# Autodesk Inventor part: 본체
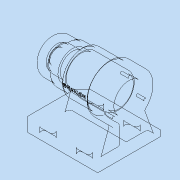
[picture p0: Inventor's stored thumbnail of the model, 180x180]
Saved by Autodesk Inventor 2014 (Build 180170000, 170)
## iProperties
Created: 2017-09
Part Number: 본체
Material: 알루미늄 6061
Document SubType Name: Modeling
Designer: kb542-16
Mass: 696.175 g
Surface Area: 708.751 cm^2
Volume: 256.891 cm^3
Density: 2.71 g/cm^3
Appearance: 알루미늄 - 평지
Author: kb542-16
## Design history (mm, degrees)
sketch "스케치2"
  geometry: L1 (-56, -45)-(56, -45); L2 (56, -45)-(56, 45); L3 (56, 45)-(-56, 45); L4 (-56, 45)-(-56, -45); L5 (-56, -45)-(56, 45); L6 (56, -45)-(-56, 45); 1 further point
  constraints: 12 end point, 2 midpoint, 2 parallel, 1 horizontal, 1 perpendicular
  dimensions: "d4" = 112 distance between parallel lines of L4 L2; "d5" = 90 distance between parallel lines of L1 L3
extrude "돌출1" new body sketch "스케치2" distance "d6" = 8; taper "d7" = 0 deg
chamfer "모따기1" distance "d8" = 12; stored, may be unused: second distance "d9" = 2, angle "d10" = 45 deg
sketch "스케치3"
  geometry: L1 (-32, 34)-(-20, 34); L2 (-32, 30)-(-20, 30); L3 (-20, 38)-(-32, 38); L4 (20, 34)-(32, 34); L5 (20, 30)-(32, 30); L6 (32, 38)-(20, 38); L7 (56, -45)-(56, 45) reference; A1 r 4 centre (-32, 34) between (-32, 38) and (-32, 30); A2 r 4 centre (-20, 34) between (-20, 30) and (-20, 38); A3 r 4 centre (20, 34) between (20, 38) and (20, 30); A4 r 4 centre (32, 34) between (32, 30) and (32, 38); 3 further points
  constraints: 16 end point, 8 point on circle, 8 tangent, 4 centre point, 3 equal length, 2 midpoint, 1 horizontal
  dimensions: "d11" = 12 distance of L1.end L1.start; "d12" = 4 radius of A1; "d13" = 34 vertical distance of point (0, 0) point (-26, 34); "d15" = 24 distance from line of L7 L4.end; "d16" = 40 distance of L4.start L1.end; "d17" = 12 distance of L5.start L5.end; "d18" = 4 radius of A4; "d19" = 34 vertical distance of point (0, 0) point (26, 34)
extrude "돌출2" cut sketch "스케치3" stored distance "d20" = 8; taper "d21" = 0 deg
sketch "스케치4"
  geometry: L1 (56, 8)-(-36.778, 12.784); L2 (-56, 8)-(44, 8) reference; L3 (-56, 78)-(-56, 8); L4 (-56, 8)-(34, 8); L5 (34, 8)-(15.244, 78); L6 (15.244, 78)-(-56, 78); 2 further points
  constraints: 10 end point, 2 perpendicular, 1 coincident, 1 parallel
  dimensions: "d25" = 70 distance between parallel lines of L2 L6; "d28" = 105 deg angle of L4 L5; "d79" = 22 distance of L1.start L4.end
extrude "돌출3" join sketch "스케치4" stored distance "d29" = 8; taper "d30" = 0 deg
sketch "스케치5"
  geometry: L1 (-56, 70)-(-28, 70); L2 (-28, 70)-(-28, 104); L3 (-28, 104)-(-56, 104); L4 (-56, 104)-(-56, 70); L5 (-28, 70)-(11, 70); L6 (11, 70)-(11, 100); L7 (11, 100)-(-28, 100); L8 (-28, 100)-(-28, 70); L9 (11, 70)-(31, 70); L10 (31, 70)-(31, 97); L11 (31, 97)-(11, 97); L12 (11, 97)-(11, 70); L13 (31, 70)-(56, 70); L14 (56, 70)-(56, 95); L15 (56, 95)-(31, 95); L16 (31, 95)-(31, 70); L17 (-56, 0)-(-56, 8) reference; L18 (44, 0)-(-56, 0) reference; 3 further points
  constraints: 32 end point, 8 parallel, 4 horizontal, 4 perpendicular, 2 midpoint, 1 vertical alignment
  dimensions: "d32" = 70 distance between parallel lines of L1 L18; "d33" = 112 distance between parallel lines of L14 L4; "d38" = 84 distance between parallel lines of L2 L14; "d39" = 45 distance between parallel lines of L12 L14; "d40" = 25 distance between parallel lines of L14 L16; "d41" = 68 diameter of L3 L1; "d42" = 60 diameter of L7 L5; "d43" = 54 diameter of L11 L9; "d44" = 50 diameter of L15 L13
revolve "회전1" sketch "스케치5" stored, may be unused: angle "d45" = 90 deg
sketch "스케치6"
  geometry: L1 (-8, 0)-(-8, 41) reference; L2 (-8, 49)-(-8, 90) reference; L3 (-36.236, 49)-(-8, 49) reference; L4 (-8, 10)-(-8, 80); L5 (-8, 80)-(-60.695, 60.821); L6 (-60.695, 60.821)-(-60.695, 29.179); L7 (-60.695, 29.179)-(-8, 10); 1 further point
  constraints: 8 end point, 1 collinear, 1 parallel, 1 perpendicular
  dimensions: "d46" = 10 distance of L2.end L4.end; "d47" = 110 deg angle of L5 L2; "d48" = 10 distance of L1.start L4.start; "d49" = 110 deg angle of L1 L7; "d50" = 52.69516 distance between parallel lines of L2 L6
extrude "돌출4" join sketch "스케치6" distance "d51" = 8; taper "d52" = 0 deg
sketch "스케치7"
  geometry: L1 (-56, 43.992)-(-56, 104) reference; L2 (-56, 70)-(-41, 70); L3 (-41, 70)-(-41, 91); L4 (-41, 91)-(-56, 91); L5 (-56, 91)-(-56, 70); L6 (-41, 70)-(13, 70); L7 (13, 70)-(13, 94); L8 (13, 94)-(-41, 94); L9 (-41, 94)-(-41, 70); L10 (13, 70)-(25, 70); L11 (25, 70)-(25, 91); L12 (25, 91)-(13, 91); L13 (13, 91)-(13, 70); L14 (25, 70)-(43, 70); L15 (43, 70)-(43, 87.5); L16 (43, 87.5)-(25, 87.5); L17 (25, 87.5)-(25, 70); L18 (43, 70)-(47, 70); L19 (47, 70)-(47, 86); L20 (47, 86)-(43, 86); L21 (43, 86)-(43, 70); L22 (47, 70)-(50, 70); L23 (50, 70)-(50, 80.5); L24 (50, 80.5)-(47, 80.5); L25 (47, 80.5)-(47, 70); L26 (44, 0)-(-56, 0) reference; 1 further point
  constraints: 48 end point, 12 parallel, 6 horizontal, 6 perpendicular, 1 point on line
  dimensions: "d53" = 70 distance between parallel lines of L26 L2; "d54" = 42 diameter of L4 L2; "d55" = 48 diameter of L8 L6; "d56" = 42 diameter of L12 L10; "d57" = 35 diameter of L16 L14; "d58" = 32 diameter of L20 L18; "d59" = 21 diameter of L24 L22; "d60" = 15 distance between parallel lines of L5 L3; "d61" = 54 distance between parallel lines of L7 L9; "d62" = 12 distance between parallel lines of L13 L17; "d63" = 18 distance between parallel lines of L17 L21; "d64" = 4 distance between parallel lines of L15 L19; "d65" = 3 distance between parallel lines of L19 L23
revolve "회전2" sketch "스케치7" stored, may be unused: angle "d66" = 90 deg
sketch "스케치8" dims "d67" = 52
  geometry: C1 r 21 at (-70, 45) reference; 2 further points
  constraints: 1 horizontal alignment, 2 other
hole "구멍1" sketch "스케치8" at (-96, 45) diameter "d68" = 3.242; stored, may be unused: countersink angle "d72" = 90 deg, drill point angle "d74" = 118 deg; dims "d69" = 8, "d70" = 4, "d71" = 2, "d73" = 11
fillet "모깎기1" dims "d78" = 9
fillet "모깎기2" dims "d80" = 3
fillet "모깎기3" dims "d81" = 3
fillet "모깎기4" dims "d82" = 3
fillet "모깎기5" dims "d83" = 3
fillet "모깎기6" dims "d84" = 3
fillet "모깎기7" dims "d85" = 3
chamfer "모따기2" distance "d86" = 1; stored, may be unused: second distance "d87" = 2, angle "d88" = 45 deg
fillet "모깎기8" dims "d89" = 0.3
node "작업 평면2"
sketch "스케치10"
  geometry: L1 (56, 104)-(56, 43.992) reference; L2 (-44, 0)-(56, 0) reference; 2 further points
  constraints: 1 other
  dimensions: "d90" = 48 distance from line of L1 point (8, 70); "d91" = 70 distance from line of L2 point (8, 70)
feature "엠보싱1" sketch "스케치10" dims "d4" = 112, "d5" = 90, "d11" = 12, "d12" = 4, "d13" = 34, "d15" = 24, "d16" = 40, "d17" = 12, "d18" = 4, "d19" = 34, "d92" = 0.5, "d93" = 0
fillet "모깎기9" dims "d94" = 3
fillet "모깎기10" dims "d95" = 3
fillet "모깎기11" dims "d96" = 3
fillet "모깎기12" dims "d97" = 3
node "솔리드1"
mirror "대칭1"
pattern_circular "원형 패턴1" dims angle "d76" = 360 deg
